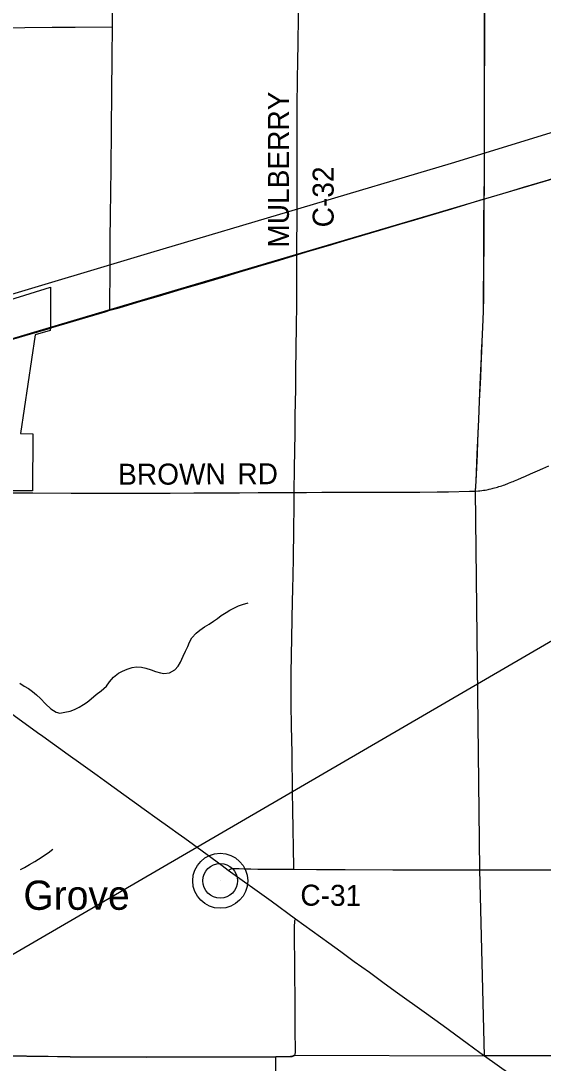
# Model space of a CAD drawing. Extents: x -87 to 2145, y -2128 to 440.
# Drawn here: x 49 to 86.3, y -1230.4 to -1156 of the extents above; entities that cross this region are included whole.
import ezdxf

# ---------------------------------------------------------------- set-up
doc = ezdxf.new("R2010")
doc.units = 0
for name, color, linetype in [('GM_X_Corporation', 7, 'Continuous'), ('GM_X_County_Road', 7, 'Continuous'), ('GM_X_County_Road_Text', 7, 'Continuous'), ('GM_X_Minor_River', 7, 'Continuous'), ('GM_X_Rail_Line', 7, 'Continuous'), ('GM_X_State_Route', 7, 'Continuous'), ('GM_X_Township', 7, 'Continuous'), ('GM_X_Township_Road', 7, 'Continuous'), ('GM_X_Township_Text', 7, 'Continuous'), ('GM_X_Unincorporated', 7, 'Continuous'), ('GM_X_Unincorporated_Location', 7, 'Continuous'), ('GM_X_Unincorporated_Text', 7, 'Continuous'), ('GM_X_US_Route', 7, 'Continuous'), ('SC_Scratch1', 7, 'Continuous')]:
    doc.layers.add(name, color=color, linetype=linetype)

msp = doc.modelspace()

# ---------------------------------------------------------------- linework, layer by layer
at = {"layer": 'GM_X_Corporation'}
msp.add_lwpolyline([(46.716, -1176.348), (51.091, -1175.003), (51.093, -1177.902), (51.071, -1178.091), (50.007, -1178.413), (48.959, -1185.446), (49.827, -1185.459), (49.796, -1189.544), (44.056, -1189.526)], dxfattribs=at)
at = {"layer": 'GM_X_County_Road'}
for points in [[(68.679, -1172.7), (68.718, -1169.422), (68.71, -1165.486), (68.712, -1163.353), (68.717, -1162.5), (68.72, -1161.943), (68.764, -1158.711), (68.772, -1157.776), (68.803, -1155.546), (68.832, -1153.348), (68.845, -1152.249), (68.87, -1150.166), (68.891, -1147.985), (68.906, -1145.492), (68.916, -1144.721), (68.926, -1143.967), (68.935, -1143.031), (68.962, -1141.621), (68.979, -1140.785), (68.998, -1138.751), (69.012, -1136.8)], [(81.456, -1189.553), (81.653, -1189.543), (81.766, -1189.532), (81.904, -1189.516), (82.018, -1189.499), (82.126, -1189.482), (82.248, -1189.46), (82.348, -1189.441), (82.432, -1189.423), (82.531, -1189.402), (82.634, -1189.378), (82.719, -1189.356), (82.816, -1189.33), (82.916, -1189.302), (83.018, -1189.271), (83.122, -1189.239), (83.224, -1189.206), (83.333, -1189.169), (83.44, -1189.133), (83.535, -1189.098), (83.628, -1189.063), (83.708, -1189.033), (83.804, -1188.996), (83.914, -1188.952), (84.032, -1188.905), (84.142, -1188.859), (84.229, -1188.822), (84.463, -1188.722), (84.735, -1188.607), (85.021, -1188.486), (85.379, -1188.332), (85.87, -1188.117), (86.26, -1187.948), (86.694, -1187.763)], [(44.063, -1189.655), (45.586, -1189.667), (45.997, -1189.668), (49.443, -1189.678), (49.82, -1189.677)], [(49.82, -1189.677), (52.58, -1189.696), (53.876, -1189.697), (54.778, -1189.702), (55.484, -1189.704), (57.289, -1189.71), (59.635, -1189.703), (61.341, -1189.688), (62.063, -1189.679), (64.245, -1189.672), (64.589, -1189.67), (65.935, -1189.659), (67.148, -1189.656), (68.281, -1189.658), (68.5, -1189.658)], [(68.5, -1189.658), (69.38, -1189.658), (70.479, -1189.643), (71.972, -1189.638), (73.416, -1189.625), (75.008, -1189.624), (77.468, -1189.624), (78.715, -1189.614), (79.52, -1189.603), (81.013, -1189.568), (81.456, -1189.553)], [(63.789, -1216.629), (63.954, -1216.529), (63.989, -1216.512), (64.021, -1216.501), (64.073, -1216.494), (64.123, -1216.492), (64.19, -1216.494), (64.57, -1216.503), (64.935, -1216.512), (65.391, -1216.523), (65.89, -1216.533), (68.21, -1216.544), (68.469, -1216.546)], [(68.469, -1216.546), (70.098, -1216.555), (72.137, -1216.557), (75.545, -1216.577), (77.585, -1216.583), (79.54, -1216.579), (81.765, -1216.59)], [(81.765, -1216.59), (82.227, -1216.592), (83.841, -1216.592), (85.662, -1216.579), (87.825, -1216.592), (90.141, -1216.601), (92.446, -1216.596), (94.989, -1216.599), (95.284, -1216.598)]]:
    msp.add_lwpolyline(points, dxfattribs=at)
at = {"layer": 'GM_X_Minor_River'}
for points in [[(57.233, -1202.091), (57.593, -1202.128), (57.903, -1202.193), (58.271, -1202.32), (58.6, -1202.425), (58.939, -1202.531), (59.199, -1202.576), (59.591, -1202.532), (59.965, -1202.318), (60.2, -1202.062), (60.385, -1201.774), (60.573, -1201.336), (60.739, -1200.968), (60.905, -1200.641), (61.03, -1200.342), (61.176, -1200.034), (61.502, -1199.699), (61.756, -1199.492), (62.091, -1199.238), (62.425, -1199.043), (62.739, -1198.838), (63.023, -1198.642), (63.287, -1198.436), (63.632, -1198.212), (63.905, -1198.046), (64.178, -1197.92), (64.531, -1197.756), (64.814, -1197.65), (65.207, -1197.537)], [(48.904, -1203.253), (49.212, -1203.468), (49.529, -1203.654), (49.806, -1203.859), (50.103, -1204.085), (50.39, -1204.35), (50.724, -1204.737), (51.109, -1205.094), (51.486, -1205.341), (51.755, -1205.406), (52.107, -1205.342), (52.499, -1205.258), (52.802, -1205.133), (53.146, -1204.968), (53.459, -1204.793), (53.723, -1204.617), (53.997, -1204.372), (54.343, -1204.067), (54.719, -1203.803), (55.085, -1203.478), (55.311, -1203.161), (55.597, -1202.825), (55.942, -1202.55), (56.225, -1202.405), (56.578, -1202.261), (56.931, -1202.136), (57.233, -1202.091)], [(48.953, -1216.564), (49.246, -1216.418), (49.581, -1216.204), (49.985, -1215.99), (50.238, -1215.834), (50.928, -1215.365), (51.253, -1215.109)]]:
    msp.add_lwpolyline(points, dxfattribs=at)
at = {"layer": 'GM_X_Rail_Line'}
for points in [[(32.645, -1179.993), (33.938, -1179.677), (35.52, -1179.34), (58.27, -1172.536), (79.726, -1166.155), (101.875, -1159.348), (126.551, -1151.893), (148.59, -1145.271), (154.705, -1143.429), (159.327, -1142.564), (162.774, -1141.883), (166.327, -1141.143), (170.107, -1140.276), (172.235, -1139.734), (175.075, -1139.439), (176.226, -1139.455)], [(33.834, -1182.995), (50.78, -1177.944), (58.706, -1175.591), (68.608, -1172.671), (93.903, -1165.212), (126.008, -1155.832), (151.467, -1148.459), (176.207, -1141.169), (176.948, -1140.939), (177.24, -1140.847), (177.432, -1140.708), (177.517, -1140.503), (177.453, -1139.385)]]:
    msp.add_lwpolyline(points, dxfattribs=at)
at = {"layer": 'GM_X_State_Route'}
for points in [[(82.093, -1229.874), (81.76, -1229.637), (80.855, -1228.984), (79.129, -1227.732), (77.77, -1226.756), (75.872, -1225.379), (74.933, -1224.69), (73.867, -1223.924), (72.788, -1223.149), (71.821, -1222.443), (70.972, -1221.825), (68.584, -1220.108), (66.842, -1218.834), (63.789, -1216.629), (63.35, -1216.29), (61.917, -1215.248), (60.676, -1214.362), (60.215, -1214.02), (59.613, -1213.594), (58.719, -1212.955), (57.776, -1212.272), (57.097, -1211.784), (56.337, -1211.239), (54.954, -1210.242), (54.425, -1209.854), (53.263, -1209.026), (52.359, -1208.374), (50.547, -1207.074), (50.174, -1206.805), (47.167, -1204.639)], [(103.567, -1245.188), (103.41, -1245.077), (102.625, -1244.515), (101.878, -1243.981), (100.743, -1243.183), (100.162, -1242.777), (99.624, -1242.384), (99.062, -1241.986), (98.032, -1241.255), (96.508, -1240.171), (94.464, -1238.715), (94.293, -1238.593), (93.463, -1238.001), (91.083, -1236.31), (85.884, -1232.583), (82.093, -1229.874)]]:
    msp.add_lwpolyline(points, dxfattribs=at)
at = {"layer": 'GM_X_Township'}
msp.add_lwpolyline([(107.137, -1229.857), (82.086, -1229.86), (81.759, -1216.576), (81.45, -1189.539), (81.483, -1188.84), (81.574, -1186.908), (81.615, -1185.951), (81.66, -1184.924), (81.678, -1184.465), (81.735, -1183.121), (81.812, -1181.4), (81.867, -1179.974), (81.882, -1179.646), (81.919, -1178.892), (81.988, -1177.319), (82.01, -1176.696), (82.027, -1175.696), (82.047, -1173.4), (82.052, -1172.219), (82.05, -1170.972), (82.053, -1169.807), (82.062, -1169.168), (82.07, -1168.689), (82.078, -1168.222), (82.083, -1167.369), (82.084, -1166.647), (82.086, -1165.104), (82.084, -1163.446), (82.086, -1162.792), (82.09, -1162.004), (82.09, -1160.983), (82.098, -1157.427), (82.101, -1154.655)], dxfattribs=at)
at = {"layer": 'GM_X_Township_Road'}
for points in [[(82.076, -1168.703), (82.084, -1168.236), (82.089, -1167.383), (82.09, -1166.662), (82.092, -1165.119), (82.09, -1163.461), (82.092, -1162.806), (82.097, -1162.019), (82.097, -1160.998), (82.104, -1157.441), (82.107, -1154.669), (82.12, -1153.11), (82.126, -1151.88), (82.135, -1150.371), (82.157, -1147.415), (82.174, -1145.793), (82.207, -1142.393), (82.227, -1140.477), (82.255, -1138.129), (82.272, -1136.857)], [(55.514, -1156.421), (55.521, -1155.339), (55.527, -1154.486), (55.54, -1153.584), (55.558, -1151.796), (55.568, -1150.91), (55.621, -1145.564), (55.628, -1144.52)], [(45.352, -1157.213), (45.45, -1156.87), (45.481, -1156.777), (45.512, -1156.701), (45.554, -1156.631), (45.601, -1156.581), (45.642, -1156.551), (45.696, -1156.529), (45.778, -1156.513), (45.889, -1156.507), (47.532, -1156.487), (49.271, -1156.469), (51.206, -1156.447), (52.862, -1156.432), (55.514, -1156.421)], [(55.338, -1176.653), (55.337, -1176.466), (55.335, -1176.121), (55.346, -1173.972), (55.358, -1171.577), (55.382, -1169.888), (55.422, -1166.558), (55.458, -1163.753), (55.461, -1162.884), (55.473, -1161.932), (55.483, -1160.67), (55.495, -1159.03), (55.5, -1158.554), (55.514, -1156.421)], [(81.456, -1189.553), (81.489, -1188.854), (81.58, -1186.922), (81.621, -1185.965), (81.666, -1184.938), (81.684, -1184.479), (81.741, -1183.135), (81.818, -1181.414), (81.873, -1179.988), (81.889, -1179.66), (81.925, -1178.906), (81.995, -1177.333), (82.016, -1176.71), (82.033, -1175.71), (82.054, -1173.414), (82.059, -1172.233), (82.056, -1170.986), (82.059, -1169.821), (82.068, -1169.182), (82.076, -1168.703)], [(68.5, -1189.658), (68.501, -1189.636), (68.531, -1187.914), (68.563, -1185.42), (68.578, -1184.173), (68.61, -1182.254), (68.621, -1180.991), (68.667, -1177.792), (68.679, -1176.267), (68.681, -1174.692), (68.684, -1173.757), (68.68, -1172.863), (68.679, -1172.7)], [(68.469, -1216.546), (68.467, -1216.389), (68.412, -1212.306), (68.388, -1211.026), (68.346, -1208.271), (68.315, -1206.319), (68.293, -1204.777), (68.278, -1203.316), (68.285, -1202.561), (68.335, -1200.019), (68.388, -1197.378), (68.407, -1196.591), (68.439, -1194.409), (68.463, -1192.244), (68.485, -1190.669), (68.5, -1189.658)], [(68.492, -1229.838), (68.508, -1229.827), (68.546, -1229.782), (68.568, -1229.744), (68.579, -1229.695), (68.586, -1229.647), (68.569, -1227.895), (68.564, -1227.009), (68.533, -1222.813), (68.531, -1221.878), (68.524, -1220.55), (68.533, -1220.34), (68.542, -1220.268), (68.555, -1220.201), (68.584, -1220.108)], [(33.326, -1229.824), (34.928, -1229.822), (38.027, -1229.829), (39.717, -1229.831), (40.767, -1229.84), (42.374, -1229.851), (43.932, -1229.853), (46.377, -1229.862), (49.395, -1229.886), (51.595, -1229.913)], [(51.595, -1229.913), (52.496, -1229.925), (57.975, -1229.951), (64.554, -1229.937), (67.186, -1229.924)], [(67.185, -1243.179), (67.186, -1243.029), (67.189, -1242.334), (67.193, -1241.431), (67.195, -1240.841), (67.192, -1238.28), (67.185, -1236.671), (67.184, -1235.802), (67.182, -1235.096), (67.181, -1234.817), (67.188, -1234.014), (67.185, -1231.635), (67.187, -1230.502), (67.186, -1229.924)], [(67.186, -1229.924), (68.069, -1229.916), (68.247, -1229.912), (68.343, -1229.902), (68.419, -1229.881), (68.459, -1229.862), (68.492, -1229.838)]]:
    msp.add_lwpolyline(points, dxfattribs=at)
at = {"layer": 'GM_X_Township_Text'}
msp.add_lwpolyline([(46.37, -1229.848), (49.389, -1229.871), (52.49, -1229.911), (57.969, -1229.937), (64.548, -1229.923), (67.18, -1229.91), (68.062, -1229.902), (68.241, -1229.897), (68.337, -1229.888), (68.412, -1229.867), (68.453, -1229.848), (68.486, -1229.824), (82.086, -1229.86), (81.759, -1216.576), (81.45, -1189.539), (81.483, -1188.84), (81.574, -1186.908), (81.615, -1185.951), (81.66, -1184.924), (81.678, -1184.465), (81.735, -1183.121), (81.812, -1181.4), (81.867, -1179.974), (81.882, -1179.646), (81.919, -1178.892), (81.988, -1177.319), (82.01, -1176.696), (82.027, -1175.696), (82.047, -1173.4), (82.052, -1172.219), (82.05, -1170.972), (82.053, -1169.807), (82.062, -1169.168), (82.07, -1168.689), (82.078, -1168.222), (82.083, -1167.369), (82.084, -1166.647), (82.086, -1165.104), (82.084, -1163.446), (82.086, -1162.792), (82.09, -1162.004), (82.09, -1160.983), (82.098, -1157.427), (82.101, -1154.655)], dxfattribs=at)
at = {"layer": 'GM_X_Unincorporated'}
for radius in [1.964, 1.245]:
    msp.add_circle((63.213, -1217.37), radius, dxfattribs=at)
at = {"layer": 'GM_X_Unincorporated_Location'}
msp.add_line((63.213, -1217.37), (63.213, -1217.37), dxfattribs=at)
at = {"layer": 'GM_X_US_Route'}
for points in [[(82.076, -1168.703), (82.182, -1168.671), (83.81, -1168.185), (84.869, -1167.866), (86.416, -1167.408), (88.076, -1166.911), (90.685, -1166.139), (93.139, -1165.418), (94.602, -1164.991), (98.07, -1163.971), (99.971, -1163.418), (102.113, -1162.79), (103.298, -1162.443), (104.655, -1162.046), (105.663, -1161.752), (106.77, -1161.436), (107.51, -1161.224), (108.245, -1161.008)], [(51.124, -1177.909), (52.103, -1177.611), (53.786, -1177.115), (54.996, -1176.752), (55.338, -1176.653), (55.989, -1176.464), (57.295, -1176.08), (58.806, -1175.638), (60.457, -1175.146), (61.779, -1174.759), (63.477, -1174.254), (64.294, -1174.009), (66.15, -1173.459), (66.888, -1173.236), (67.455, -1173.071), (68.679, -1172.7), (69.386, -1172.486), (71.198, -1171.961), (71.888, -1171.751), (73.317, -1171.319), (74.622, -1170.93), (76.037, -1170.512), (77.106, -1170.19), (78.883, -1169.665), (79.747, -1169.405), (82.076, -1168.703)], [(42.499, -1180.444), (43.775, -1180.064), (43.998, -1179.998), (45.445, -1179.575), (45.541, -1179.547), (45.593, -1179.532), (46.695, -1179.207), (47.082, -1179.093), (47.893, -1178.852), (49.275, -1178.442), (51.099, -1177.916), (51.124, -1177.909)]]:
    msp.add_lwpolyline(points, dxfattribs=at)
at = {"layer": 'SC_Scratch1'}
msp.add_line((902.065, -726.16), (-86.991, -1301.38), dxfattribs=at)

# ---------------------------------------------------------------- texts
at = {"layer": 'GM_X_County_Road_Text'}
for s, rotation, p in [('MULBERRY', 90, (68.12, -1172.183)), ('C-32', 90, (71.317, -1170.731)), ('BROWN', 0.18344, (55.926, -1189.105)), ('RD', 0.48881, (64.446, -1189.083)), ('C-31', 359.65721, (68.935, -1219.141))]:
    msp.add_text(s, height=1.5, rotation=rotation, dxfattribs=at).set_placement(p)
at = {"layer": 'GM_X_Unincorporated_Text'}
msp.add_text('Mulberry Grove', height=2.085, rotation=0.00001, dxfattribs=at).set_placement((37.536, -1219.44))

doc.saveas('drawing.dxf')
